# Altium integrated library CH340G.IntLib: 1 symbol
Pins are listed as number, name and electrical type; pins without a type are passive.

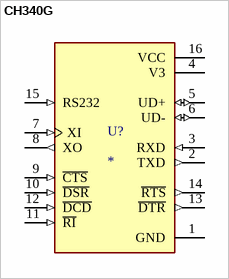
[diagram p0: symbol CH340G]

## CH340G
designator U?
MP: CH340G
footprint SOIC127P600X180-16N
pins: 1 GND (power), 2 TXD (out), 3 RXD (in), 4 V3 (power), 5 UD+ (io), 6 UD- (io), 7 XI (in), 8 XO (out), 9 ~{CTS} (in), 10 ~{DSR} (in), 11 ~{RI} (in), 12 ~{DCD} (in), 13 ~{DTR} (out), 14 ~{RTS} (out), 15 RS232 (in), 16 VCC (power)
